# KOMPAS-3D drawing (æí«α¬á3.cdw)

Views: Вид 1
Referenced files: Сборочный_нессиметр.cdw
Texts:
  Редуктор двухступенчатый
  Noncommercial version
  корпус
  маслоотражатели
  размеры
  N9/Js9
  1. Крутящий момент на тихоходном валу - 6,3 кН м
  2. Передаточное число - 29,7
  3. Частота вращения быстроходного вала - 243 мин -1
  4. Частота вращения тихоходного вала - 18,2 мин -1
  5. Срок службы - 7665 ч.
  max
  min
  Размеры для справок.
  Залить в редуктор 15 л. масла И-Г-С-100 ГОСТ 17479.4-87.
  В подшипники тихоходного вала заложить смазку Литол-24.
  Редуктор обкатать на стенде в течении 10 мин. Течь масла
  через уплотнения не допускается.
  В собранном редукторе валы должны проворачиваться от руки
  легко, плавно и без заеданий.
  Головки маслоуказателя и спускной пробки окрасить в
  красный цвет.
  Наружные поверхности, за исключением выступающих концов
  валов окрасить атмосферостойкой эмалью.
  Винт М24 х 80 ГОСТ 11738-84
  Винт
  ГОСТ
  Шайба 24 Н ГОСТ 6402-70
  Шайба пружинная
  Шайба
  ОКМА-30.06.01.00.01
  Корпус
  ОКМА-30.06.01.01.00.СБ
  Щуп масломерный
  ОКМА-30.06.01.00.03
  Прокладка
  ОКМА-30.06.01.00.04
  Крышка лючка
  ОКМА-30.06.01.00.05
  Сапун
  ОКМА-30.06.01.00.06
  Пробка
  ОКМА-30.06.01.00.07
  ОКМА-30.06.01.00.08
  Вал-шестерня
  ОКМА-30.06.01.00.09
  Колесо зубчатое
  ОКМА-30.06.01.00.10
  Кольцо упорное
  ОКМА-30.06.01.00.11
  ОКМА-30.06.01.00.12
  Кольцо маслоотражающее
  ОКМА-30.06.01.00.13
  ОКМА-30.06.01.00.14
  ОКМА-30.06.01.00.15
  Крышка глухая
  ОКМА-30.06.01.00.16
  Крышка проходная
  ОКМА-30.06.01.00.17
  Винт М10 х 28 ГОСТ 11644-75
  Винт М16 х 50 ГОСТ 11738-84
  ОКМА-30.06.01.00.18
  Кольцо сальниковое
  ОКМА-30.06.01.00.19
  Болт М10 х 25 ГОСТ 7796-70
  Болт
  Болт М12 х 30 ГОСТ 7796-70
  Крышка 2-100 41 ГОСТ 11641-73
  Шпилька
  Крышка 22-100 ГОСТ 18511-73
  Подшипник 50309  ГОСТ 2893-82
  Подшипник 50314  ГОСТ 2893-82
  Подшипник 124  ГОСТ 8338-75
  Шайба 10 Н ГОСТ 6402-70
  Шайба 12 Н ГОСТ 6402-70
  Шайба 16 Н ГОСТ 6402-70
  Штифт 16 х 70 ГОСТ 3129-70
  Штифт
  Хим.Окс.прм
  Шпонка 12 8 70 ГОСТ23360-78
  Шпонка 32 28 100 ГОСТ10748-79
  Шпонка 28 25 160 ГОСТ10748-79
  Шпонка 20 18 63 ГОСТ10748-79
  ОКМА-30.06.01.00.02
  Крышка
  Редуктор
  двухступенчатый
  ДГТУ
Dimensions and other numbers on the sheet: 8 отв.; 26; 250; 227; 140; 82; 165; 617; 30; 720; 120; 70; 71; 45; 100; 150; 180; 1444; 2 отв.; 16; 10 отв.; 24; 220; 295; 385; 125; 600,4; 12; 44; 40; 110; 28; 1; 2; 3; 4; 5; 6; 7; 8; 9; 10; 11; 13; 14; 15; 17; 18; 27; 32; 29; 33; 19; 20; 25; 31; 34; 35; 36; 37; 38; 43; 39; 41; 42; 50; -6g; 84; 65Г; 029; 75; 76; 1:2,5; 20.05.06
